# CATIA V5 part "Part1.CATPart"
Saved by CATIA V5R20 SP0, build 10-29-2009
Part number: Part1
Bounding box of the stored display mesh (mm): x -75 to 75, y 0 to 40, z -40 to 40
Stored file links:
  E:\Ehsan\Catia\Tamrin\DMU\2\Part1.CATPart
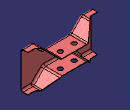
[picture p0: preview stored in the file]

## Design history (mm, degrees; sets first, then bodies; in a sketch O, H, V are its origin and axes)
Body1 (main body)
  Sketch1 on zx-plane, origin (0, 0, 0), H (-1, 0, 0), V (0, 0, 1)
    line L1 (75, 40) -> (75, -40)
    line L2 (75, -40) -> (-75, -40)
    line L3 (-75, -40) -> (-75, 40)
    line L4 (-75, 40) -> (75, 40)
    distance L2 L4 = 80
    distance L1 L3 = 150
    vertical: L1 V, L3 V
    horizontal: L2 H, L4 H
    equidistance: L1 L3 O, L2 L4 O
  Pad1: profile Sketch1, direction (0, 1, 0), length 40
  Sketch2 on zx-plane, origin (0, 0, 0), H (-1, 0, 0), V (0, 0, 1)
    line L1 (0, 16.5) -> (0, 61.3379)
    point P1 (0, 16.5)
    distance P1 H = 16.5
    coincidence: P1 V
    vertical: L1 V
  Pocket1: profile Sketch2, direction (0, 1, 0), length 40, thin wall 57
  Draft1: PullDir face of Pocket1, Angle 45, SupportToDraft (face of Pocket1; face of Pocket1), Neutral face of Pocket1
  Fillet1: radius 5, on edge [face of Pocket1 | face of Pocket1] (x2); edge [face of Pocket1 | face of Pad1 from Sketch1.L4] (x2)
  Split1: SplitPlane xy-plane
  Mirror1: of the body so far, about face of Split1
  Fillet2: radius 5, on edge [face of Pad1 | face of Pad1 from Sketch1.L4] (x2); edge [face of Pad1 | face of Fillet1] (x2); edge [face of Pocket1 | face of Pad1] (x3); edge [face of Fillet1 | face of Pad1] (x2); edge [face of Mirror1 | face of Pad1] (x4); edge [face of Pad1 | face of Mirror1] (x5)
  Shell1: IntOffset 1, Face (face of Pad1; face of Pad1; face of Pad1), ExtOffset 0
  Sketch3 on xy-plane, origin (0, 0, 0), H (1, 0, 0), V (0, 1, 0)
    line L1 (-30, 40) -> (30, 40)
    point P1 (0, 40)
    point P2 (-30, 40)
    point P3 (30, 40)
    line L2 (30, 40) -> (59.7938, 15)
    point P4 (59.7938, 15)
    line L3 (59.7938, 15) -> (85.2427, 15)
    point P5 (59.7938, 15)
    point P6 (85.2427, 15)
    point P7 (-85.2427, 15)
    point P8 (-59.7938, 15)
    line L4 (-59.7938, 15) -> (-85.2427, 15)
    point P9 (-59.7938, 15)
    point P10 (-30, 40)
    line L5 (-30, 40) -> (-59.7938, 15)
    distance P1 H = 40
    length L1 = 60
    distance P4 H = 15
    angle L2 H = 40
    midpoint: L1 P1
    coincidence: P1 V, P5 L2, P2 P10, P4 P5, P8 P9
    horizontal: L1 H, L3 H
    symmetry: P6 P7 V, P5 P8 V, L3 L4 V, P4 P9 V, P3 P10 V, L2 L5 V
  Pocket2: profile Sketch3, direction (0, 0, -1), through (limit type 3), opposite side through (limit type 3)
  Sketch4 on face of Pocket1, origin (0, 0, 16.5), H (1, 0, 0), V (0, 1, 0)
    circle A1 centre (15, 25) radius 5
    point P1 (15, 25)
    circle A2 centre (-15, 25) radius 5
    distance P1 H = 25
    distance P1 V = 15
    radius A1 = 5
    symmetry: A1 A2 V
  Pocket3: profile Sketch4, direction (0, 0, 1), through (limit type 3)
